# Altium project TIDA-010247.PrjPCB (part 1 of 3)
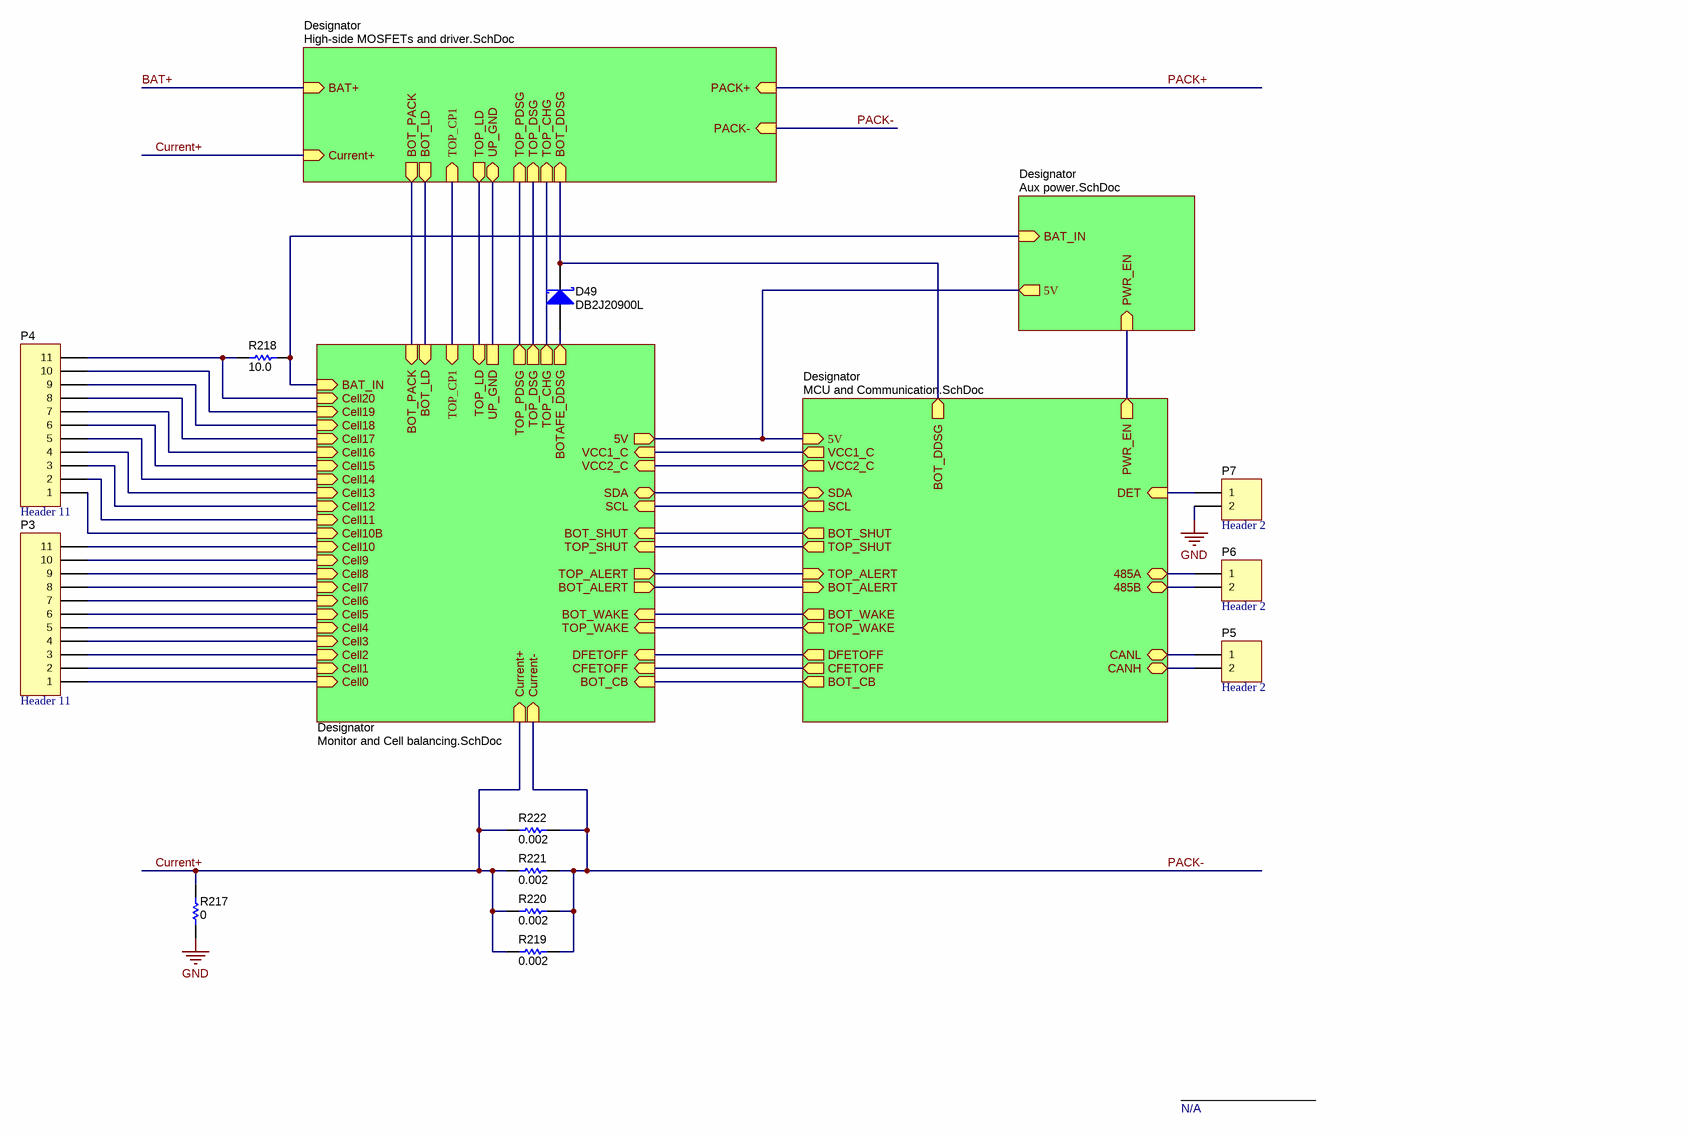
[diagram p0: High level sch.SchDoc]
TID: TIDA-010247; TechSupport: http://www.ti.com/support; SCH_Rev: E1; PRJ_Title: Up to 32s high side N-MOSFET; PRJ_Number: TIDA-010247; PRJ_Engineer: Ryan Tan; PRJ_Customer: Public Release; PCB_Rev: E1; PCB_Layout: Ryan Tan; CopyrightYear: 2021/11
7 sheets, 434 parts. Net scope: hierarchical (ports join the sheet entries above them; power ports are global).
Board file: v1.PcbDoc
Sheets:
  High level sch.SchDoc
    Designator = Monitor and Cell balancing.SchDoc
    Designator = Aux power.SchDoc
    Designator = MCU and Communication.SchDoc
    Designator = High-side MOSFETs and driver.SchDoc
    Designator = EVM_Hardware.SchDoc
    Designator = CoverSheet.SchDoc

## Sheet High level sch.SchDoc
size 431 x 279 mm; Date: Not shown in title block; ApprovedBy: Not shown in title block; CheckedBy: Not shown in title block; Author: Not shown in title block; CompanyName: Not shown in title block; Engineer: Not shown in title block; Organization: Not shown in title block; Address1: Not shown in title block; Address2: Not shown in title block; Address3: Not shown in title block; Address4: Not shown in title block; DocumentNumber: 2; Revision: Use project parameter SCH_Rev; SheetNumber: 2; SheetTotal: 7; PageSetup: Record=PageOptions¦CenterHorizontal=True¦CenterVertical=True¦PrintScale=1.00¦XCorrection=1.00¦YCorrection=1.00¦PrintKind=0¦BorderSize=5000000¦LeftOffset=0¦BottomOffset=0¦Orientation=2¦PaperLength=1000¦PaperWidth=1000¦Scale=100¦PaperSource=15¦PrintQuality=600¦MediaType=1¦DitherType=10¦PaperKind=Letter¦PrintScaleMode=1

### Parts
D49  DB2J20900L  [SOD-323F]
P3  Header 11  [XH Connector 11P]
P4  Header 11  [XH Connector 11P]
P5  Header 2  [HDR1X2]
P6  Header 2  [HDR1X2]
P7  Header 2  [HDR1X2]
R217  ValueDisplayed: 0  [0603]  (hidden comment: CRCW06030000Z0EA)
R218  ValueDisplayed: 10.0  [0603]  (hidden comment: RC0603FR-0710RL)
R219  ValueDisplayed: 0.002  [2512]  (hidden comment: CSNL2512FT2L00)
R220  ValueDisplayed: 0.002  [2512]  (hidden comment: CSNL2512FT2L00)
R221  ValueDisplayed: 0.002  [2512]  (hidden comment: CSNL2512FT2L00)
R222  ValueDisplayed: 0.002  [2512]  (hidden comment: CSNL2512FT2L00)

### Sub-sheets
Designator = Monitor and Cell balancing.SchDoc: Current+ (in), Current- (in), Cell0 (in), Cell15 (in), Cell1 (in), Cell16 (in), Cell3 (in), Cell6 (in), Cell2 (in), SDA (bidir), SCL (in), Cell11 (in), Cell10 (in), Cell7 (in), Cell12 (in), Cell9 (in), Cell4 (in), Cell8 (in), Cell5 (in), Cell13 (in), Cell14 (in), Cell17 (in), Cell18 (in), Cell20 (in), Cell19 (in), 5V (out), BOT_LD (in), BOT_SHUT (in), BOT_ALERT (out), BOT_WAKE (in), TOP_ALERT (out), TOP_SHUT (in), TOP_WAKE (in), BOT_PACK (in), DFETOFF (in), CFETOFF (in), BAT_IN (in), TOP_PDSG (out), TOP_DSG (out), TOP_CHG (out), TOP_LD (in), BOTAFE_DDSG (out), VCC2_C (in), VCC1_C (in), BOT_CB (in), UP_GND, Cell10B (in), TOP_CP1 (in)
Designator = Aux power.SchDoc: PWR_EN (in), BAT_IN (in), 5V (out)
Designator = MCU and Communication.SchDoc: PWR_EN (out), 485A (bidir), 485B (bidir), SCL (out), SDA (bidir), TOP_ALERT (in), BOT_SHUT (out), CANL (bidir), TOP_SHUT (out), TOP_WAKE (out), BOT_WAKE (out), BOT_ALERT (in), CANH (bidir), DFETOFF (out), CFETOFF (out), BOT_DDSG (out), VCC1_C (out), VCC2_C (out), BOT_CB (out), DET (in), 5V (in)
Designator = High-side MOSFETs and driver.SchDoc: PACK+ (in), BAT+ (in), BOT_LD (out), PACK- (in), BOT_PACK (out), TOP_DSG (in), TOP_LD (out), TOP_CHG (in), UP_GND (bidir), BOT_DDSG (in), TOP_PDSG (in), Current+ (in), TOP_CP1 (in)
Designator = EVM_Hardware.SchDoc: no entries
Designator = CoverSheet.SchDoc: no entries

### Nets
GND: P7.2 R217.1
UP_GND: sheet Designator/UP_GND, sheet Designator/UP_GND
5V: sheet Designator/5V, sheet Designator/5V, sheet Designator/5V
485A: P6.1 ; sheet Designator/485A
485B: P6.2 ; sheet Designator/485B
BAT_IN: R218.1 ; sheet Designator/BAT_IN, sheet Designator/BAT_IN
BOT_ALERT: sheet Designator/BOT_ALERT, sheet Designator/BOT_ALERT
BOT_CB: sheet Designator/BOT_CB, sheet Designator/BOT_CB
BOT_DDSG: D49.1(K) ; sheet Designator/BOT_DDSG, sheet Designator/BOT_DDSG
BOT_LD: sheet Designator/BOT_LD, sheet Designator/BOT_LD
BOT_PACK: sheet Designator/BOT_PACK, sheet Designator/BOT_PACK
BOT_SHUT: sheet Designator/BOT_SHUT, sheet Designator/BOT_SHUT
BOT_WAKE: sheet Designator/BOT_WAKE, sheet Designator/BOT_WAKE
BOTAFE_DDSG: D49.2(A) ; sheet Designator/BOTAFE_DDSG
CANH: P5.2 ; sheet Designator/CANH
CANL: P5.1 ; sheet Designator/CANL
Cell0: P3.1 ; sheet Designator/Cell0
Cell1: P3.2 ; sheet Designator/Cell1
Cell2: P3.3 ; sheet Designator/Cell2
Cell3: P3.4 ; sheet Designator/Cell3
Cell4: P3.5 ; sheet Designator/Cell4
Cell5: P3.6 ; sheet Designator/Cell5
Cell6: P3.7 ; sheet Designator/Cell6
Cell7: P3.8 ; sheet Designator/Cell7
Cell8: P3.9 ; sheet Designator/Cell8
Cell9: P3.10 ; sheet Designator/Cell9
Cell10: P3.11 ; sheet Designator/Cell10
Cell10B: P4.1 ; sheet Designator/Cell10B
Cell11: P4.2 ; sheet Designator/Cell11
Cell12: P4.3 ; sheet Designator/Cell12
Cell13: P4.4 ; sheet Designator/Cell13
Cell14: P4.5 ; sheet Designator/Cell14
Cell15: P4.6 ; sheet Designator/Cell15
Cell16: P4.7 ; sheet Designator/Cell16
Cell17: P4.8 ; sheet Designator/Cell17
Cell18: P4.9 ; sheet Designator/Cell18
Cell19: P4.10 ; sheet Designator/Cell19
Cell20: P4.11 R218.2 ; sheet Designator/Cell20
CFETOFF: sheet Designator/CFETOFF, sheet Designator/CFETOFF
Current+: R217.2 R219.1 R220.1 R221.1 R222.1 ; sheet Designator/Current+, sheet Designator/Current+
DET: P7.1 ; sheet Designator/DET
DFETOFF: sheet Designator/DFETOFF, sheet Designator/DFETOFF
PACK-: R219.2 R220.2 R221.2 R222.2 ; sheet Designator/Current-, sheet Designator/PACK-
PWR_EN: sheet Designator/PWR_EN, sheet Designator/PWR_EN
SCL: sheet Designator/SCL, sheet Designator/SCL
SDA: sheet Designator/SDA, sheet Designator/SDA
TOP_ALERT: sheet Designator/TOP_ALERT, sheet Designator/TOP_ALERT
TOP_CHG: sheet Designator/TOP_CHG, sheet Designator/TOP_CHG
TOP_CP1: sheet Designator/TOP_CP1, sheet Designator/TOP_CP1
TOP_DSG: sheet Designator/TOP_DSG, sheet Designator/TOP_DSG
TOP_LD: sheet Designator/TOP_LD, sheet Designator/TOP_LD
TOP_PDSG: sheet Designator/TOP_PDSG, sheet Designator/TOP_PDSG
TOP_SHUT: sheet Designator/TOP_SHUT, sheet Designator/TOP_SHUT
TOP_WAKE: sheet Designator/TOP_WAKE, sheet Designator/TOP_WAKE
VCC1_C: sheet Designator/VCC1_C, sheet Designator/VCC1_C
VCC2_C: sheet Designator/VCC2_C, sheet Designator/VCC2_C

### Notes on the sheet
- N/A

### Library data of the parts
D49 = DB2J20900L: Diode, Schottky, 20 V, 0.5 A, SOD-323F; Manufacturer: Panasonic; U/M: EA; Vf_V: 0.5; Value: 20V; Value1: 0.5A; Value2: 0.5V; Vr_V: 20; TJmax_C: 125; SizeAreaWB_mm2: 7.875; SizeArea_mm2: 3.125; SizeX_mm: 2.5; SizeY_mm: 1.25; SizeZ_mm: 0.8; AEC Category: Q101; AEC Qualified: N; Green_Lifecycle: Not Set; Green_REACh: Incomplete
P3 P4 = Header 11: Header, 11-Pin
P5-P7 = Header 2: Header, 2-Pin
R217 = CRCW06030000Z0EA: RES, 0, 5%, 0.1 W, 0603; Manufacturer: Vishay-Dale; CompType: Resistor; Value: 0; Value_Code: 0000; Tolerance_%: 5; Power_W: 0.1; Value2: 0.1W; VDC_V: 75; TempCo: 200 ppm/C; SizeArea_mm2: 1.28; SizeX_mm: 1.6; SizeY_mm: 0.8; SizeZ_mm: 1; EIA_Code: E24; U/M: EA; AEC Category: Q200; Green_Lifecycle: Active; Green_REACh: Passed
R218 = RC0603FR-0710RL: RES, 10.0, 1%, 0.1 W, 0603; Manufacturer: Yageo America; CompType: Resistor; Value: 10.0; Res_ohm: 10; Value_Code: 10R0; Tolerance_%: 1; Power_W: 0.1; Value2: 0.1W; VDC_V: 150; TempCo: 200 ppm/C; SizeArea_mm2: 1.28; SizeX_mm: 1.6; SizeY_mm: 0.8; EIA_Code: E96; U/M: EA; AEC Category: Q200; Green_Lifecycle: Active; Green_REACh: Passed
R219-R222 = CSNL2512FT2L00: RES, 0.002, 1%, 2 W, 2512; Manufacturer: Stackpole Electronics Inc; CompType: Resistor; Value: 0.002; Value_Code: 2L000; Tolerance_%: 1; Power_W: 2; Value2: 2W; VDC_V: 200; TempCo: 50 ppm/C; SizeArea_mm2: 20.16; SizeX_mm: 6.3; SizeY_mm: 3.2; SizeZ_mm: 0.71; U/M: EA; AEC Category: Q200

## Sheet Monitor and Cell balancing.SchDoc
size A2; Date: Not shown in title block; ApprovedBy: Not shown in title block; CheckedBy: Not shown in title block; Author: Not shown in title block; CompanyName: Not shown in title block; Engineer: Not shown in title block; Organization: Not shown in title block; Address1: Not shown in title block; Address2: Not shown in title block; Address3: Not shown in title block; Address4: Not shown in title block; DocumentNumber: 6; Revision: Use project parameter SCH_Rev; SheetNumber: 6; SheetTotal: 7; PageSetup: Record=PageOptions¦CenterHorizontal=True¦CenterVertical=True¦PrintScale=1.00¦XCorrection=1.00¦YCorrection=1.00¦PrintKind=0¦BorderSize=5000000¦LeftOffset=0¦BottomOffset=0¦Orientation=2¦PaperLength=1000¦PaperWidth=1000¦Scale=100¦PaperSource=15¦PrintQuality=600¦MediaType=1¦DitherType=10¦PaperKind=Letter¦PrintScaleMode=1
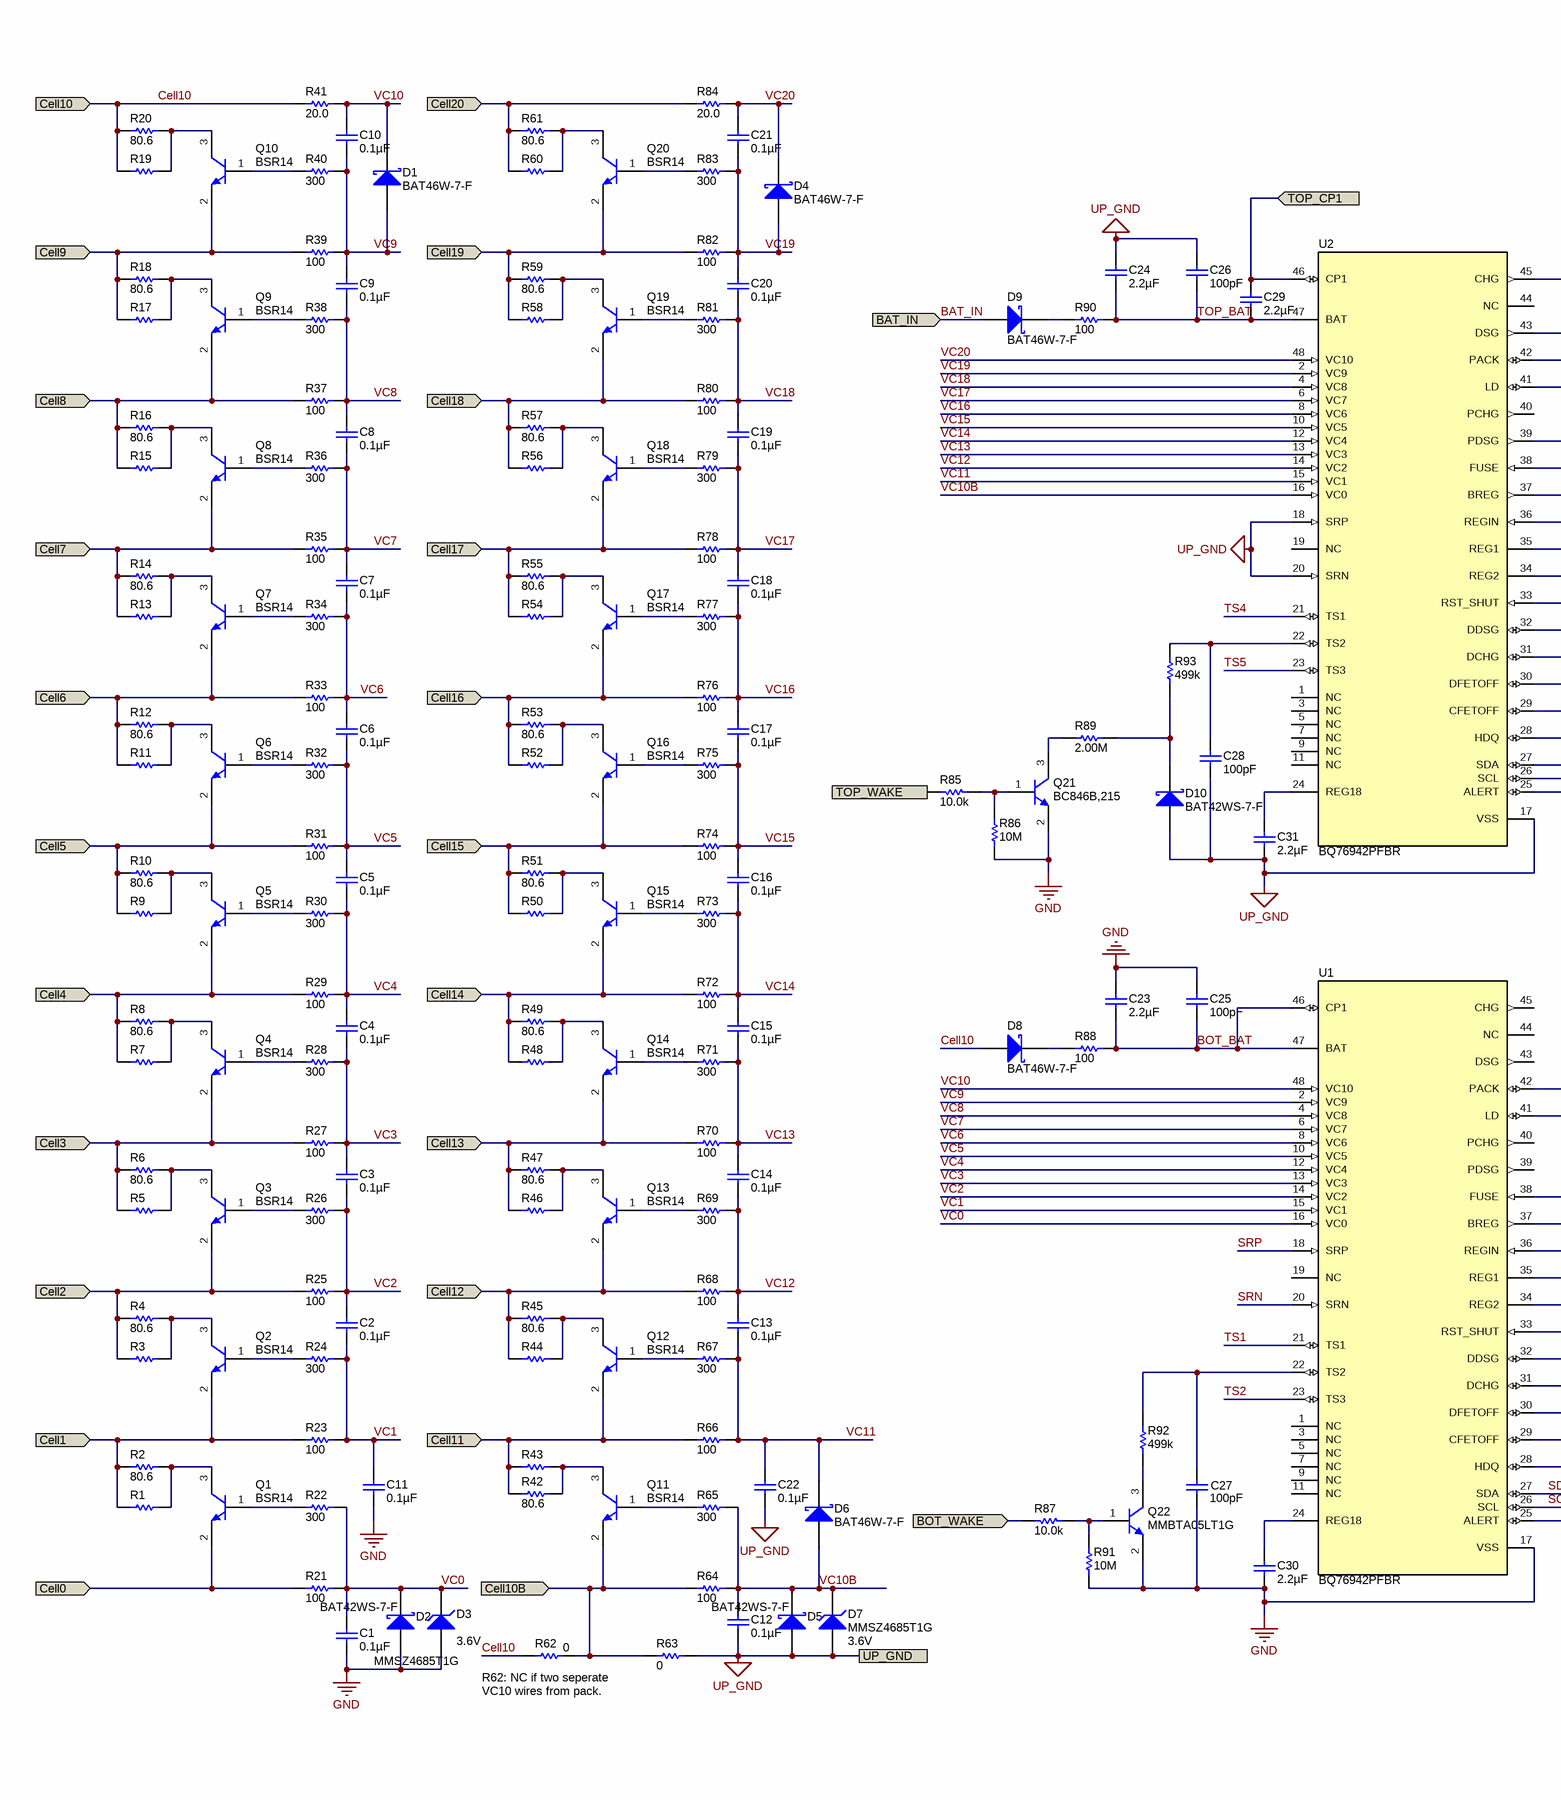
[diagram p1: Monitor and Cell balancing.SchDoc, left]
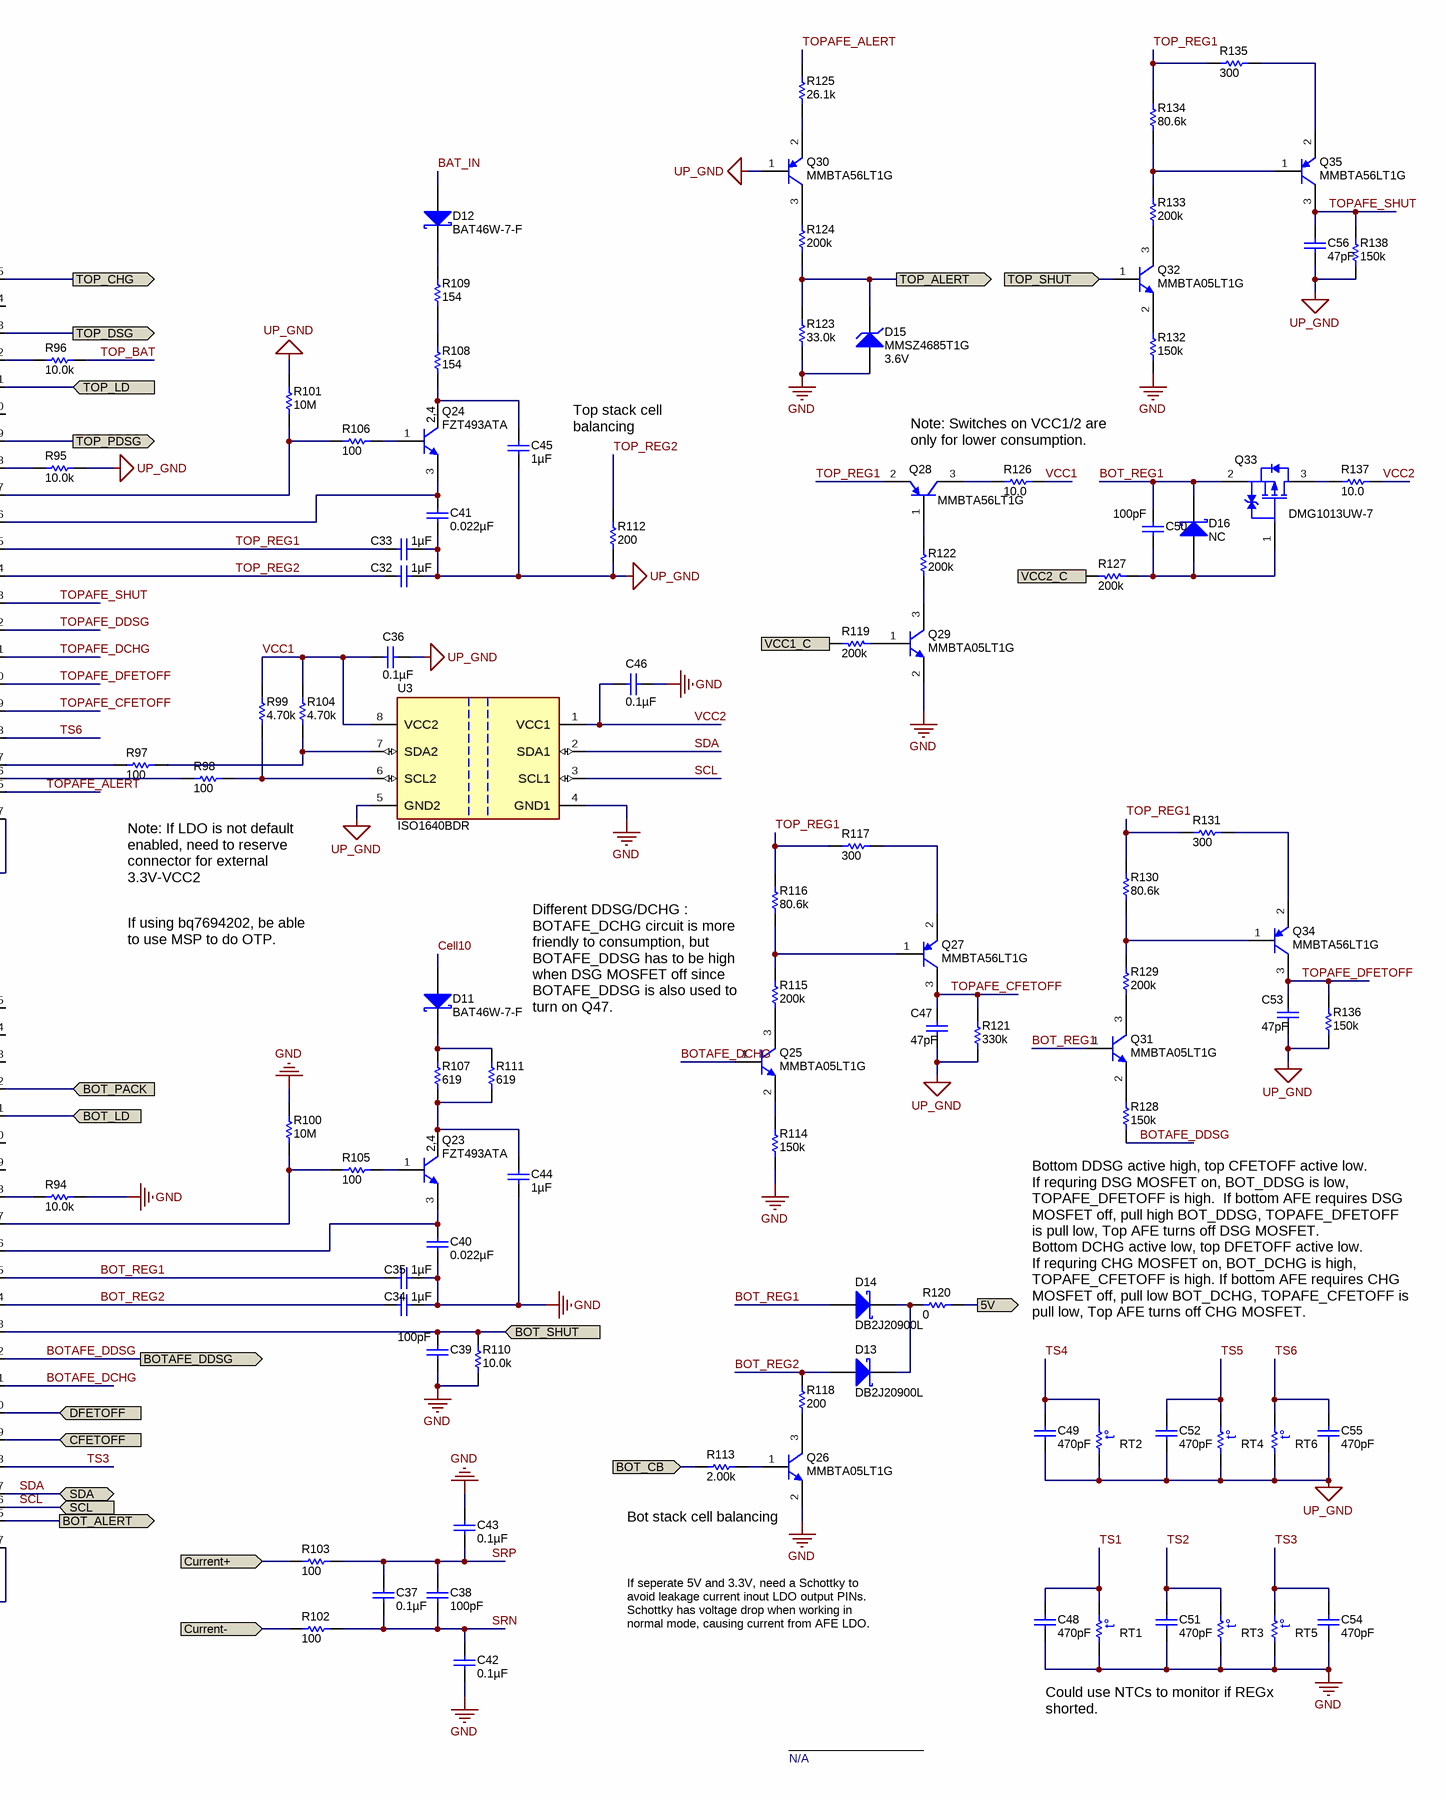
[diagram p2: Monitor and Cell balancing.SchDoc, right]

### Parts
C1  ValueDisplayed: 0.1µF  [0402]  (hidden comment: GRM155R71E104KE14D)
C2  ValueDisplayed: 0.1µF  [0402]  (hidden comment: GRM155R71E104KE14D)
C3  ValueDisplayed: 0.1µF  [0402]  (hidden comment: GRM155R71E104KE14D)
C4  ValueDisplayed: 0.1µF  [0402]  (hidden comment: GRM155R71E104KE14D)
C5  ValueDisplayed: 0.1µF  [0402]  (hidden comment: GRM155R71E104KE14D)
C6  ValueDisplayed: 0.1µF  [0402]  (hidden comment: GRM155R71E104KE14D)
C7  ValueDisplayed: 0.1µF  [0402]  (hidden comment: GRM155R71E104KE14D)
C8  ValueDisplayed: 0.1µF  [0402]  (hidden comment: GRM155R71E104KE14D)
C9  ValueDisplayed: 0.1µF  [0402]  (hidden comment: GRM155R71E104KE14D)
C10  ValueDisplayed: 0.1µF  [0402]  (hidden comment: GRM155R71E104KE14D)
C11  ValueDisplayed: 0.1µF  [0603S]  (hidden comment: GRM188R71H104KA93D)
C12  ValueDisplayed: 0.1µF  [0402]  (hidden comment: GRM155R71E104KE14D)
C13  ValueDisplayed: 0.1µF  [0402]  (hidden comment: GRM155R71E104KE14D)
C14  ValueDisplayed: 0.1µF  [0402]  (hidden comment: GRM155R71E104KE14D)
C15  ValueDisplayed: 0.1µF  [0402]  (hidden comment: GRM155R71E104KE14D)
C16  ValueDisplayed: 0.1µF  [0402]  (hidden comment: GRM155R71E104KE14D)
C17  ValueDisplayed: 0.1µF  [0402]  (hidden comment: GRM155R71E104KE14D)
C18  ValueDisplayed: 0.1µF  [0402]  (hidden comment: GRM155R71E104KE14D)
C19  ValueDisplayed: 0.1µF  [0402]  (hidden comment: GRM155R71E104KE14D)
C20  ValueDisplayed: 0.1µF  [0402]  (hidden comment: GRM155R71E104KE14D)
C21  ValueDisplayed: 0.1µF  [0402]  (hidden comment: GRM155R71E104KE14D)
C22  ValueDisplayed: 0.1µF  [0603S]  (hidden comment: GRM188R71H104KA93D)
C23  ValueDisplayed: 2.2µF  [1206_190]  (hidden comment: C1206X225K101TX)
C24  ValueDisplayed: 2.2µF  [1206_190]  (hidden comment: C1206X225K101TX)
C25  ValueDisplayed: 100pF  [0603]  (hidden comment: GRM1885C2A101JA01D)
C26  ValueDisplayed: 100pF  [0603]  (hidden comment: GRM1885C2A101JA01D)
C27  ValueDisplayed: 100pF  [0603]  (hidden comment: GRM1885C2A101JA01D)
C28  ValueDisplayed: 100pF  [0603]  (hidden comment: GRM1885C2A101JA01D)
C29  ValueDisplayed: 2.2µF  [0805_HV]  (hidden comment: GRM21BR71E225KA73L)
C30  ValueDisplayed: 2.2µF  [0603]  (hidden comment: EMK107BB7225MA-T)
C31  ValueDisplayed: 2.2µF  [0603]  (hidden comment: EMK107BB7225MA-T)
C32  ValueDisplayed: 1µF  [0603]  (hidden comment: GCM188R71C105KA64D)
C33  ValueDisplayed: 1µF  [0603]  (hidden comment: GCM188R71C105KA64D)
C34  ValueDisplayed: 1µF  [0603]  (hidden comment: GCM188R71C105KA64D)
C35  ValueDisplayed: 1µF  [0603]  (hidden comment: GCM188R71C105KA64D)
C36  ValueDisplayed: 0.1µF  [0603]  (hidden comment: GRM188R71H104KA93D)
C37  ValueDisplayed: 0.1µF  [0603]  (hidden comment: GRM188R71H104KA93D)
C38  ValueDisplayed: 100pF  [0603]  (hidden comment: GRM1885C2A101JA01D)
C39  ValueDisplayed: 100pF  [0603]  (hidden comment: GRM1885C2A101JA01D)
C40  ValueDisplayed: 0.022µF  [0603S]  (hidden comment: GRM188R71H223KA01D)
C41  ValueDisplayed: 0.022µF  [0603]  (hidden comment: GRM188R71H223KA01D)
C42  ValueDisplayed: 0.1µF  [0603]  (hidden comment: GRM188R71H104KA93D)
C43  ValueDisplayed: 0.1µF  [0603]  (hidden comment: GRM188R71H104KA93D)
C44  ValueDisplayed: 1µF  [1206_180]  (hidden comment: C3216X7R2A105K160AA)
C45  ValueDisplayed: 1µF  [1206_180]  (hidden comment: C3216X7R2A105K160AA)
C46  ValueDisplayed: 0.1µF  [0603]  (hidden comment: GRM188R71H104KA93D)
C47  ValueDisplayed: 47pF  [0603]  (hidden comment: GRM1885C1H470JA01D)
C48  ValueDisplayed: 470pF  [0603]  (hidden comment: GRM188R71H471KA01D)
C49  ValueDisplayed: 470pF  [0603]  (hidden comment: GRM188R71H471KA01D)
C50  ValueDisplayed: 100pF  [0603]  (hidden comment: GRM1885C2A101JA01D)
C51  ValueDisplayed: 470pF  [0603]  (hidden comment: GRM188R71H471KA01D)
C52  ValueDisplayed: 470pF  [0603]  (hidden comment: GRM188R71H471KA01D)
C53  ValueDisplayed: 47pF  [0603]  (hidden comment: GRM1885C1H470JA01D)
C54  ValueDisplayed: 470pF  [0603]  (hidden comment: GRM188R71H471KA01D)
C55  ValueDisplayed: 470pF  [0603]  (hidden comment: GRM188R71H471KA01D)
C56  ValueDisplayed: 47pF  [0603]  (hidden comment: GRM1885C1H470JA01D)
D1  BAT46W-7-F  [SOD-123]
D2  BAT42WS-7-F  [SOD-323]
D3  MMSZ4685T1G  value 3.6V  [SOD-123]
D4  BAT46W-7-F  [SOD-123]
D5  BAT42WS-7-F  [SOD-323]
D6  BAT46W-7-F  [SOD-123]
D7  MMSZ4685T1G  value 3.6V  [SOD-123]
D8  BAT46W-7-F  [SOD-123]
D9  BAT46W-7-F  [SOD-123]
D10  BAT42WS-7-F  [SOD-323]
D11  BAT46W-7-F  [SOD-123]
D12  BAT46W-7-F  [SOD-123]
D13  DB2J20900L  [SOD-323F]
D14  DB2J20900L  [SOD-323F]
D15  MMSZ4685T1G  value 3.6V  [SOD-123]
D16  NC  [SOD-323]
Q1  BSR14  [SOT-23]
Q2  BSR14  [SOT-23]
Q3  BSR14  [SOT-23]
Q4  BSR14  [SOT-23]
Q5  BSR14  [SOT-23]
Q6  BSR14  [SOT-23]
Q7  BSR14  [SOT-23]
Q8  BSR14  [SOT-23]
Q9  BSR14  [SOT-23]
Q10  BSR14  [SOT-23]
Q11  BSR14  [SOT-23]
Q12  BSR14  [SOT-23]
Q13  BSR14  [SOT-23]
Q14  BSR14  [SOT-23]
Q15  BSR14  [SOT-23]
Q16  BSR14  [SOT-23]
Q17  BSR14  [SOT-23]
Q18  BSR14  [SOT-23]
Q19  BSR14  [SOT-23]
Q20  BSR14  [SOT-23]
Q21  BC846B,215  [SOT-23]
Q22  MMBTA05LT1G  [SOT-23]
Q23  FZT493ATA  [SOT-223]
Q24  FZT493ATA  [SOT-223]
Q25  MMBTA05LT1G  [SOT-23]
Q26  MMBTA05LT1G  [SOT-23]
Q27  MMBTA56LT1G  [SOT-23]
Q28  MMBTA56LT1G  [SOT-23]
Q29  MMBTA05LT1G  [SOT-23]
Q30  MMBTA56LT1G  [SOT-23]
Q31  MMBTA05LT1G  [SOT-23]
Q32  MMBTA05LT1G  [SOT-23]
Q33  DMG1013UW-7  [SOT-323]
Q34  MMBTA56LT1G  [SOT-23]
Q35  MMBTA56LT1G  [SOT-23]
R1  CRCW120680R6FKEA  [1206]  (value not drawn)
R2  ValueDisplayed: 80.6  [1206]  (hidden comment: CRCW120680R6FKEA)
R3  CRCW120680R6FKEA  [1206]  (value not drawn)
R4  ValueDisplayed: 80.6  [1206]  (hidden comment: CRCW120680R6FKEA)
R5  CRCW120680R6FKEA  [1206]  (value not drawn)
R6  ValueDisplayed: 80.6  [1206]  (hidden comment: CRCW120680R6FKEA)
R7  CRCW120680R6FKEA  [1206]  (value not drawn)
R8  ValueDisplayed: 80.6  [1206]  (hidden comment: CRCW120680R6FKEA)
R9  CRCW120680R6FKEA  [1206]  (value not drawn)
R10  ValueDisplayed: 80.6  [1206]  (hidden comment: CRCW120680R6FKEA)
R11  CRCW120680R6FKEA  [1206]  (value not drawn)
R12  ValueDisplayed: 80.6  [1206]  (hidden comment: CRCW120680R6FKEA)
R13  CRCW120680R6FKEA  [1206]  (value not drawn)
R14  ValueDisplayed: 80.6  [1206]  (hidden comment: CRCW120680R6FKEA)
R15  CRCW120680R6FKEA  [1206]  (value not drawn)
R16  ValueDisplayed: 80.6  [1206]  (hidden comment: CRCW120680R6FKEA)
R17  CRCW120680R6FKEA  [1206]  (value not drawn)
R18  ValueDisplayed: 80.6  [1206]  (hidden comment: CRCW120680R6FKEA)
R19  CRCW120680R6FKEA  [1206]  (value not drawn)
R20  ValueDisplayed: 80.6  [1206]  (hidden comment: CRCW120680R6FKEA)
R21  ValueDisplayed: 100  [0603]  (hidden comment: CRCW0603100RFKEA)
R22  ValueDisplayed: 300  [0603]  (hidden comment: CRCW0603300RJNEA)
R23  ValueDisplayed: 100  [0603]  (hidden comment: CRCW0603100RFKEA)
R24  ValueDisplayed: 300  [0603]  (hidden comment: CRCW0603300RJNEA)
R25  ValueDisplayed: 100  [0603]  (hidden comment: CRCW0603100RFKEA)
R26  ValueDisplayed: 300  [0603]  (hidden comment: CRCW0603300RJNEA)
R27  ValueDisplayed: 100  [0603]  (hidden comment: CRCW0603100RFKEA)
R28  ValueDisplayed: 300  [0603]  (hidden comment: CRCW0603300RJNEA)
R29  ValueDisplayed: 100  [0603]  (hidden comment: CRCW0603100RFKEA)
R30  ValueDisplayed: 300  [0603]  (hidden comment: CRCW0603300RJNEA)
R31  ValueDisplayed: 100  [0603]  (hidden comment: CRCW0603100RFKEA)
R32  ValueDisplayed: 300  [0603]  (hidden comment: CRCW0603300RJNEA)
R33  ValueDisplayed: 100  [0603]  (hidden comment: CRCW0603100RFKEA)
R34  ValueDisplayed: 300  [0603]  (hidden comment: CRCW0603300RJNEA)
R35  ValueDisplayed: 100  [0603]  (hidden comment: CRCW0603100RFKEA)
R36  ValueDisplayed: 300  [0603]  (hidden comment: CRCW0603300RJNEA)
R37  ValueDisplayed: 100  [0603]  (hidden comment: CRCW0603100RFKEA)
R38  ValueDisplayed: 300  [0603]  (hidden comment: CRCW0603300RJNEA)
R39  ValueDisplayed: 100  [0603]  (hidden comment: CRCW0603100RFKEA)
R40  ValueDisplayed: 300  [0603]  (hidden comment: CRCW0603300RJNEA)
R41  ValueDisplayed: 20.0  [0603]  (hidden comment: CRCW060320R0FKEA)
R42  ValueDisplayed: 80.6  [1206]  (hidden comment: CRCW120680R6FKEA)
R43  CRCW120680R6FKEA  [1206]  (value not drawn)
R44  CRCW120680R6FKEA  [1206]  (value not drawn)
R45  ValueDisplayed: 80.6  [1206]  (hidden comment: CRCW120680R6FKEA)
R46  CRCW120680R6FKEA  [1206]  (value not drawn)
R47  ValueDisplayed: 80.6  [1206]  (hidden comment: CRCW120680R6FKEA)
R48  CRCW120680R6FKEA  [1206]  (value not drawn)
R49  ValueDisplayed: 80.6  [1206]  (hidden comment: CRCW120680R6FKEA)
R50  CRCW120680R6FKEA  [1206]  (value not drawn)
R51  ValueDisplayed: 80.6  [1206]  (hidden comment: CRCW120680R6FKEA)
R52  CRCW120680R6FKEA  [1206]  (value not drawn)
R53  ValueDisplayed: 80.6  [1206]  (hidden comment: CRCW120680R6FKEA)
R54  CRCW120680R6FKEA  [1206]  (value not drawn)
R55  ValueDisplayed: 80.6  [1206]  (hidden comment: CRCW120680R6FKEA)
R56  CRCW120680R6FKEA  [1206]  (value not drawn)
R57  ValueDisplayed: 80.6  [1206]  (hidden comment: CRCW120680R6FKEA)
R58  CRCW120680R6FKEA  [1206]  (value not drawn)
R59  ValueDisplayed: 80.6  [1206]  (hidden comment: CRCW120680R6FKEA)
R60  CRCW120680R6FKEA  [1206]  (value not drawn)
R61  ValueDisplayed: 80.6  [1206]  (hidden comment: CRCW120680R6FKEA)
R62  ValueDisplayed: 0  [0603]  (hidden comment: CRCW06030000Z0EA)
R63  ValueDisplayed: 0  [0603]  (hidden comment: CRCW06030000Z0EA)
R64  ValueDisplayed: 100  [0603]  (hidden comment: CRCW0603100RFKEA)
R65  ValueDisplayed: 300  [0603]  (hidden comment: CRCW0603300RJNEA)
R66  ValueDisplayed: 100  [0603]  (hidden comment: CRCW0603100RFKEA)
R67  ValueDisplayed: 300  [0603]  (hidden comment: CRCW0603300RJNEA)
R68  ValueDisplayed: 100  [0603]  (hidden comment: CRCW0603100RFKEA)
R69  ValueDisplayed: 300  [0603]  (hidden comment: CRCW0603300RJNEA)
R70  ValueDisplayed: 100  [0603]  (hidden comment: CRCW0603100RFKEA)
R71  ValueDisplayed: 300  [0603]  (hidden comment: CRCW0603300RJNEA)
R72  ValueDisplayed: 100  [0603]  (hidden comment: CRCW0603100RFKEA)
R73  ValueDisplayed: 300  [0603]  (hidden comment: CRCW0603300RJNEA)
R74  ValueDisplayed: 100  [0603]  (hidden comment: CRCW0603100RFKEA)
R75  ValueDisplayed: 300  [0603]  (hidden comment: CRCW0603300RJNEA)
R76  ValueDisplayed: 100  [0603]  (hidden comment: CRCW0603100RFKEA)
R77  ValueDisplayed: 300  [0603]  (hidden comment: CRCW0603300RJNEA)
R78  ValueDisplayed: 100  [0603]  (hidden comment: CRCW0603100RFKEA)
R79  ValueDisplayed: 300  [0603]  (hidden comment: CRCW0603300RJNEA)
R80  ValueDisplayed: 100  [0603]  (hidden comment: CRCW0603100RFKEA)
R81  ValueDisplayed: 300  [0603]  (hidden comment: CRCW0603300RJNEA)
R82  ValueDisplayed: 100  [0603]  (hidden comment: CRCW0603100RFKEA)
R83  ValueDisplayed: 300  [0603]  (hidden comment: CRCW0603300RJNEA)
R84  ValueDisplayed: 20.0  [0603]  (hidden comment: CRCW060320R0FKEA)
R85  ValueDisplayed: 10.0k  [0603]  (hidden comment: CRCW060310K0FKEA)
R86  ValueDisplayed: 10M  [0603]  (hidden comment: CRCW060310M0JNEA)
R87  ValueDisplayed: 10.0k  [0603]  (hidden comment: CRCW060310K0FKEA)
R88  ValueDisplayed: 100  [0603]  (hidden comment: CRCW0603100RFKEA)
R89  ValueDisplayed: 2.00M  [0603]  (hidden comment: RC0603FR-072ML)
R90  ValueDisplayed: 100  [0603]  (hidden comment: CRCW0603100RFKEA)
R91  ValueDisplayed: 10M  [0603]  (hidden comment: CRCW060310M0JNEA)
R92  ValueDisplayed: 499k  [0603]  (hidden comment: CRCW0603499KFKEA)
R93  ValueDisplayed: 499k  [0603]  (hidden comment: CRCW0603499KFKEA)
R94  ValueDisplayed: 10.0k  [0603]  (hidden comment: CRCW060310K0FKEA)
R95  ValueDisplayed: 10.0k  [0603]  (hidden comment: CRCW060310K0FKEA)
R96  ValueDisplayed: 10.0k  [0603]  (hidden comment: CRCW060310K0FKEA)
R97  ValueDisplayed: 100  [0603]  (hidden comment: CRCW0603100RFKEA)
R98  ValueDisplayed: 100  [0603]  (hidden comment: CRCW0603100RFKEA)
R99  ValueDisplayed: 4.70k  [0603]  (hidden comment: RC0603FR-074K7L)
R100  ValueDisplayed: 10M  [0603]  (hidden comment: CRCW060310M0JNEA)
R101  ValueDisplayed: 10M  [0603]  (hidden comment: CRCW060310M0JNEA)
R102  ValueDisplayed: 100  [0603]  (hidden comment: CRCW0603100RFKEA)
R103  ValueDisplayed: 100  [0603]  (hidden comment: CRCW0603100RFKEA)
R104  ValueDisplayed: 4.70k  [0603]  (hidden comment: RC0603FR-074K7L)
R105  ValueDisplayed: 100  [0603]  (hidden comment: CRCW0603100RFKEA)
R106  ValueDisplayed: 100  [0603]  (hidden comment: CRCW0603100RFKEA)
R107  ValueDisplayed: 619  [1206]  (hidden comment: RC1206FR-07619RL)
R108  ValueDisplayed: 154  [1206]  (hidden comment: AC1206FR-07154RL)
R109  ValueDisplayed: 154  [1206]  (hidden comment: AC1206FR-07154RL)
R110  ValueDisplayed: 10.0k  [0603]  (hidden comment: CRCW060310K0FKEA)
R111  ValueDisplayed: 619  [1206]  (hidden comment: RC1206FR-07619RL)
R112  ValueDisplayed: 200  [2512]  (hidden comment: RC2512JK-07200RL)
R113  ValueDisplayed: 2.00k  [0603]  (hidden comment: RC0603FR-072KL)
R114  ValueDisplayed: 150k  [0603]  (hidden comment: CRCW0603150KFKEA)
R115  ValueDisplayed: 200k  [0603]  (hidden comment: CRCW0603200KFKEA)
R116  ValueDisplayed: 80.6k  [0603]  (hidden comment: CRCW060380K6FKEA)
R117  ValueDisplayed: 300  [0603]  (hidden comment: RC0603FR-07300RL)
R118  ValueDisplayed: 200  [2512]  (hidden comment: RC2512JK-07200RL)
R119  ValueDisplayed: 200k  [0603]  (hidden comment: CRCW0603200KFKEA)
R120  ValueDisplayed: 0  [0603]  (hidden comment: CRCW06030000Z0EA)
R121  ValueDisplayed: 330k  [0603]  (hidden comment: CRCW0603330KJNEA)
R122  ValueDisplayed: 200k  [0603]  (hidden comment: CRCW0603200KFKEA)
R123  ValueDisplayed: 33.0k  [0603]  (hidden comment: RC0603FR-0733KL)
R124  ValueDisplayed: 200k  [0603]  (hidden comment: CRCW0603200KFKEA)
R125  ValueDisplayed: 26.1k  [0603]  (hidden comment: CRCW060326K1FKEA)
R126  ValueDisplayed: 10.0  [0603]  (hidden comment: RC0603FR-0710RL)
R127  ValueDisplayed: 200k  [0603]  (hidden comment: CRCW0603200KFKEA)
R128  ValueDisplayed: 150k  [0603]  (hidden comment: CRCW0603150KFKEA)
R129  ValueDisplayed: 200k  [0603]  (hidden comment: CRCW0603200KFKEA)
R130  ValueDisplayed: 80.6k  [0603]  (hidden comment: CRCW060380K6FKEA)
R131  ValueDisplayed: 300  [0603]  (hidden comment: RC0603FR-07300RL)
R132  ValueDisplayed: 150k  [0603]  (hidden comment: CRCW0603150KFKEA)
R133  ValueDisplayed: 200k  [0603]  (hidden comment: CRCW0603200KFKEA)
R134  ValueDisplayed: 80.6k  [0603]  (hidden comment: CRCW060380K6FKEA)
R135  ValueDisplayed: 300  [0603]  (hidden comment: RC0603FR-07300RL)
R136  ValueDisplayed: 150k  [0603]  (hidden comment: CRCW0603150KFKEA)
R137  ValueDisplayed: 10.0  [0603]  (hidden comment: RC0603FR-0710RL)
R138  ValueDisplayed: 150k  [0603]  (hidden comment: CRCW0603150KFKEA)
RT1  MF51E103F3950  [Thermistor_103AT-2]  (value not drawn)
RT2  MF51E103F3950  [Thermistor_103AT-2]  (value not drawn)
RT3  MF51E103F3950  [Thermistor_103AT-2]  (value not drawn)
RT4  MF51E103F3950  [Thermistor_103AT-2]  (value not drawn)
RT5  MF51E103F3950  [Thermistor_103AT-2]  (value not drawn)
RT6  MF51E103F3950  [Thermistor_103AT-2]  (value not drawn)
U1  BQ76942PFBR  [PFB0048A_N]
U2  BQ76942PFBR  [PFB0048A_N]
U3  ISO1640BDR  [D0008A-MFG]

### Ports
5V (out), BAT_IN (in), BOT_ALERT (out), BOT_CB (in), BOT_LD (in), BOT_PACK (in), BOT_SHUT (in), BOT_WAKE (in), BOTAFE_DDSG (out), Cell0 (in), Cell1 (in), Cell2 (in), Cell3 (in), Cell4 (in), Cell5 (in), Cell6 (in), Cell7 (in), Cell8 (in), Cell9 (in), Cell10 (in), Cell10B (in), Cell11 (in), Cell12 (in), Cell13 (in), Cell14 (in), Cell15 (in), Cell16 (in), Cell17 (in), Cell18 (in), Cell19 (in), Cell20 (in), CFETOFF (in), Current+ (in), Current- (in), DFETOFF (in), SCL (in), SDA (bidir), TOP_ALERT (out), TOP_CHG (out), TOP_CP1 (in), TOP_DSG (out), TOP_LD (in), TOP_PDSG (out), TOP_SHUT (in), TOP_WAKE (in), UP_GND, VCC1_C (in), VCC2_C (in)

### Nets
GND: C1.2 C11.2 C23.1 C25.1 C27.2 C30.2 C34.2 C35.2 C39.2 C40.2 C42.2 C43.1 C44.2 C46.2 C48.2 C51.2 C54.2 D2.2(A) D3.2(A) D15.2(A) Q21.2(E) Q22.2(E) Q26.2(E) Q29.2(E) R86.2 R91.2 R94.1 R100.2 R110.1 R114.1 R123.1 R132.1 RT1.1 RT3.1 RT5.1 U1.17(VSS) U3.4(GND1)
UP_GND: C12.2 C22.2 C24.1 C26.1 C28.2 C31.2 C32.2 C33.2 C36.2 C41.2 C45.2 C47.2 C49.2 C52.2 C53.2 C55.2 C56.2 D5.2(A) D7.2(A) D10.2(A) Q30.1(B) R63.1 R95.1 R101.2 R112.2 R121.1 R136.1 R138.1 RT2.1 RT4.1 RT6.1 U2.17(VSS) U2.18(SRP) U2.20(SRN) U3.5(GND2) ; port UP_GND
5V: R120.2 ; port 5V
BAT_IN: D9.2(A) D12.2(A) ; port BAT_IN
BOT_ALERT: U1.25(ALERT) ; port BOT_ALERT
BOT_BAT: C23.2 C25.2 R88.2 U1.46(CP1) U1.47(BAT)
BOT_CB: R113.1 ; port BOT_CB
BOT_LD: U1.41(LD) ; port BOT_LD
BOT_PACK: U1.42(PACK) ; port BOT_PACK
BOT_REG1: C35.1 C50.1 D14.2(A) D16.1(K) Q31.1(B) Q33.2(S) U1.35(REG1)
BOT_REG2: C34.1 D13.2(A) R118.2 U1.34(REG2)
BOT_SHUT: C39.1 R110.2 U1.33(RST_SHUT) ; port BOT_SHUT
BOT_WAKE: R87.1 ; port BOT_WAKE
BOTAFE_DCHG: Q25.1(B) U1.31(DCHG)
BOTAFE_DDSG: R128.1 U1.32(DDSG) ; port BOTAFE_DDSG
Cell0: Q1.2(E) R21.1 ; port Cell0
Cell1: Q2.2(E) R1.1 R2.1 R23.1 ; port Cell1
Cell2: Q3.2(E) R3.1 R4.1 R25.1 ; port Cell2
Cell3: Q4.2(E) R5.1 R6.1 R27.1 ; port Cell3
Cell4: Q5.2(E) R7.1 R8.1 R29.1 ; port Cell4
Cell5: Q6.2(E) R9.1 R10.1 R31.1 ; port Cell5
Cell6: Q7.2(E) R11.1 R12.1 R33.1 ; port Cell6
Cell7: Q8.2(E) R13.1 R14.1 R35.1 ; port Cell7
Cell8: Q9.2(E) R15.1 R16.1 R37.1 ; port Cell8
Cell9: Q10.2(E) R17.1 R18.1 R39.1 ; port Cell9
Cell10: D8.2(A) D11.2(A) R19.1 R20.1 R41.1 R62.2 ; port Cell10
Cell10B: Q11.2(E) R62.1 R63.2 R64.1 ; port Cell10B
Cell11: Q12.2(E) R42.1 R43.1 R66.1 ; port Cell11
Cell12: Q13.2(E) R44.1 R45.1 R68.1 ; port Cell12
Cell13: Q14.2(E) R46.1 R47.1 R70.1 ; port Cell13
Cell14: Q15.2(E) R48.1 R49.1 R72.1 ; port Cell14
Cell15: Q16.2(E) R50.1 R51.1 R74.1 ; port Cell15
Cell16: Q17.2(E) R52.1 R53.1 R76.1 ; port Cell16
Cell17: Q18.2(E) R54.1 R55.1 R78.1 ; port Cell17
Cell18: Q19.2(E) R56.1 R57.1 R80.1 ; port Cell18
Cell19: Q20.2(E) R58.1 R59.1 R82.1 ; port Cell19
Cell20: R60.1 R61.1 R84.1 ; port Cell20
CFETOFF: U1.29(CFETOFF) ; port CFETOFF
Current+: R103.1 ; port Current+
DFETOFF: U1.30(DFETOFF) ; port DFETOFF
PACK-: R102.1 ; port Current-
SCL: U1.26(SCL) U3.3(SCL1) ; port SCL
SDA: U1.27(SDA) U3.2(SDA1) ; port SDA
SRN: C37.2 C38.2 C42.1 R102.2 U1.20(SRN)
SRP: C37.1 C38.1 C43.2 R103.2 U1.18(SRP)
TOP_ALERT: D15.1(K) R123.2 R124.2 ; port TOP_ALERT
TOP_BAT: C24.2 C26.2 C29.2 R90.2 R96.1 U2.47(BAT)
TOP_CHG: U2.45(CHG) ; port TOP_CHG
TOP_CP1: C29.1 U2.46(CP1) ; port TOP_CP1
TOP_DSG: U2.43(DSG) ; port TOP_DSG
TOP_LD: U2.41(LD) ; port TOP_LD
TOP_PDSG: U2.39(PDSG) ; port TOP_PDSG
TOP_REG1: C33.1 Q28.2(E) R116.2 R117.2 R130.2 R131.2 R134.2 R135.2 U2.35(REG1)
TOP_REG2: C32.1 R112.1 U2.34(REG2)
TOP_SHUT: Q32.1(B) ; port TOP_SHUT
TOP_WAKE: R85.1 ; port TOP_WAKE
TOPAFE_ALERT: R125.2 U2.25(ALERT)
TOPAFE_CFETOFF: C47.1 Q27.3(C) R121.2 U2.29(CFETOFF)
TOPAFE_DCHG: U2.31(DCHG)
TOPAFE_DDSG: U2.32(DDSG)
TOPAFE_DFETOFF: C53.1 Q34.3(C) R136.2 U2.30(DFETOFF)
TOPAFE_SHUT: C56.1 Q35.3(C) R138.2 U2.33(RST_SHUT)
TS1: C48.1 RT1.2 U1.21(TS1)
TS2: C51.1 RT3.2 U1.23(TS3)
TS3: C54.1 RT5.2 U1.28(HDQ)
TS4: C49.1 RT2.2 U2.21(TS1)
TS5: C52.1 RT4.2 U2.23(TS3)
TS6: C55.1 RT6.2 U2.28(HDQ)
VC0: C1.1 D2.1(K) D3.1(K) R21.2 R22.2 U1.16(VC0)
VC1: C2.2 C11.1 R23.2 R24.2 U1.15(VC1)
VC2: C2.1 C3.2 R25.2 R26.2 U1.14(VC2)
VC3: C3.1 C4.2 R27.2 R28.2 U1.13(VC3)
VC4: C4.1 C5.2 R29.2 R30.2 U1.12(VC4)
VC5: C5.1 C6.2 R31.2 R32.2 U1.10(VC5)
VC6: C6.1 C7.2 R33.2 R34.2 U1.8(VC6)
VC7: C7.1 C8.2 R35.2 R36.2 U1.6(VC7)
VC8: C8.1 C9.2 R37.2 R38.2 U1.4(VC8)
VC9: C9.1 C10.2 D1.2(A) R39.2 R40.2 U1.2(VC9)
VC10: C10.1 D1.1(K) R41.2 U1.48(VC10)
VC10B: C12.1 D5.1(K) D6.2(A) D7.1(K) R64.2 R65.2 U2.16(VC0)
VC11: C13.2 C22.1 D6.1(K) R66.2 R67.2 U2.15(VC1)
VC12: C13.1 C14.2 R68.2 R69.2 U2.14(VC2)
VC13: C14.1 C15.2 R70.2 R71.2 U2.13(VC3)
VC14: C15.1 C16.2 R72.2 R73.2 U2.12(VC4)
VC15: C16.1 C17.2 R74.2 R75.2 U2.10(VC5)
VC16: C17.1 C18.2 R76.2 R77.2 U2.8(VC6)
VC17: C18.1 C19.2 R78.2 R79.2 U2.6(VC7)
VC18: C19.1 C20.2 R80.2 R81.2 U2.4(VC8)
VC19: C20.1 C21.2 D4.2(A) R82.2 R83.2 U2.2(VC9)
VC20: C21.1 D4.1(K) R84.2 U2.48(VC10)
VCC1: C36.1 R99.2 R104.2 R126.2 U3.8(VCC2)
VCC1_C: R119.1 ; port VCC1_C
VCC2: C46.1 R137.2 U3.1(VCC1)
VCC2_C: R127.1 ; port VCC2_C
NetC27_1: C27.1 R92.2 U1.22(TS2)
NetC28_1: C28.1 R93.2 U2.22(TS2)
NetC30_1: C30.1 U1.24(REG18)
NetC31_1: C31.1 U2.24(REG18)
NetC40_1: C40.1 Q23.3(E) U1.36(REGIN)
NetC41_1: C41.1 Q24.3(E) U2.36(REGIN)
NetC44_1: C44.1 Q23.2(C) Q23.4(C) R107.1 R111.1
NetC45_1: C45.1 Q24.2(C) Q24.4(C) R108.1
NetC50_2: C50.2 D16.2(A) Q33.1(G) R127.2
NetD8_1: D8.1(K) R88.1
NetD9_1: D9.1(K) R90.1
NetD10_1: D10.1(K) R89.2 R93.1
NetD11_1: D11.1(K) R107.2 R111.2
NetD12_1: D12.1(K) R109.2
NetD13_1: D13.1(K) D14.1(K) R120.1
NetQ1_1: Q1.1(B) R22.1
NetQ1_3: Q1.3(C) R1.2 R2.2
NetQ2_1: Q2.1(B) R24.1
NetQ2_3: Q2.3(C) R3.2 R4.2
NetQ3_1: Q3.1(B) R26.1
NetQ3_3: Q3.3(C) R5.2 R6.2
NetQ4_1: Q4.1(B) R28.1
NetQ4_3: Q4.3(C) R7.2 R8.2
NetQ5_1: Q5.1(B) R30.1
NetQ5_3: Q5.3(C) R9.2 R10.2
NetQ6_1: Q6.1(B) R32.1
NetQ6_3: Q6.3(C) R11.2 R12.2
NetQ7_1: Q7.1(B) R34.1
NetQ7_3: Q7.3(C) R13.2 R14.2
NetQ8_1: Q8.1(B) R36.1
NetQ8_3: Q8.3(C) R15.2 R16.2
NetQ9_1: Q9.1(B) R38.1
NetQ9_3: Q9.3(C) R17.2 R18.2
NetQ10_1: Q10.1(B) R40.1
NetQ10_3: Q10.3(C) R19.2 R20.2
NetQ11_1: Q11.1(B) R65.1
NetQ11_3: Q11.3(C) R42.2 R43.2
NetQ12_1: Q12.1(B) R67.1
NetQ12_3: Q12.3(C) R44.2 R45.2
NetQ13_1: Q13.1(B) R69.1
NetQ13_3: Q13.3(C) R46.2 R47.2
NetQ14_1: Q14.1(B) R71.1
NetQ14_3: Q14.3(C) R48.2 R49.2
NetQ15_1: Q15.1(B) R73.1
NetQ15_3: Q15.3(C) R50.2 R51.2
NetQ16_1: Q16.1(B) R75.1
NetQ16_3: Q16.3(C) R52.2 R53.2
NetQ17_1: Q17.1(B) R77.1
NetQ17_3: Q17.3(C) R54.2 R55.2
NetQ18_1: Q18.1(B) R79.1
NetQ18_3: Q18.3(C) R56.2 R57.2
NetQ19_1: Q19.1(B) R81.1
NetQ19_3: Q19.3(C) R58.2 R59.2
NetQ20_1: Q20.1(B) R83.1
NetQ20_3: Q20.3(C) R60.2 R61.2
NetQ21_1: Q21.1(B) R85.2 R86.1
NetQ21_3: Q21.3(C) R89.1
NetQ22_1: Q22.1(B) R87.2 R91.1
NetQ22_3: Q22.3(C) R92.1
NetQ23_1: Q23.1(B) R105.2
NetQ24_1: Q24.1(B) R106.2
NetQ25_2: Q25.2(E) R114.2
NetQ25_3: Q25.3(C) R115.2
NetQ26_1: Q26.1(B) R113.2
NetQ26_3: Q26.3(C) R118.1
NetQ27_1: Q27.1(B) R115.1 R116.1
NetQ27_2: Q27.2(E) R117.1
NetQ28_1: Q28.1(B) R122.1
NetQ28_3: Q28.3(C) R126.1
NetQ29_1: Q29.1(B) R119.2
NetQ29_3: Q29.3(C) R122.2
NetQ30_2: Q30.2(E) R125.1
NetQ30_3: Q30.3(C) R124.1
NetQ31_2: Q31.2(E) R128.2
NetQ31_3: Q31.3(C) R129.2
NetQ32_2: Q32.2(E) R132.2
NetQ32_3: Q32.3(C) R133.2
NetQ33_3: Q33.3(D) R137.1
NetQ34_1: Q34.1(B) R129.1 R130.1
NetQ34_2: Q34.2(E) R131.1
NetQ35_1: Q35.1(B) R133.1 R134.1
NetQ35_2: Q35.2(E) R135.1
NetR94_2: R94.2 U1.38(FUSE)
NetR95_2: R95.2 U2.38(FUSE)
NetR96_2: R96.2 U2.42(PACK)
NetR97_1: R97.1 U2.27(SDA)
NetR97_2: R97.2 R104.1 U3.7(SDA2)
NetR98_1: R98.1 U2.26(SCL)
NetR98_2: R98.2 R99.1 U3.6(SCL2)
NetR100_1: R100.1 R105.1 U1.37(BREG)
NetR101_1: R101.1 R106.1 U2.37(BREG)
NetR108_2: R108.2 R109.1

Not connected (* = marked no-connect by the designer): U1 1(NC) 3(NC) 5(NC) 7(NC) 9(NC) 11(NC) 19(NC) 39(PDSG) 40(PCHG) 43(DSG) 44(NC) 45(CHG); U2 1(NC) 3(NC) 5(NC) 7(NC) 9(NC) 11(NC) 19(NC) 40(PCHG) 44(NC)

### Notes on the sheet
- Top stack cell balancing
- Note: Switches on VCC1/2 are only for lower consumption.
- Note: If LDO is not default enabled, need to reserve connector for external 3.3V-VCC2
- If using bq7694202, be able to use MSP to do OTP.
- Different DDSG/DCHG :
  BOTAFE_DCHG circuit is more friendly to consumption, but BOTAFE_DDSG has to be high when DSG MOSFET off since
  BOTAFE_DDSG is also used to turn on Q47.
- (near R128) Bottom DDSG active high, top CFETOFF active low.
  If requring DSG MOSFET on, BOT_DDSG is low, TOPAFE_DFETOFF is high.  If bottom AFE requires DSG MOSFET off, pull high BOT_DDSG, TOPAFE_DFETOFF is pull low, Top AFE turns off DSG MOSFET.
  Bottom DCHG active low, top DFETOFF active low.
  If requring CHG MOSFET on, BOT_DCHG is high, TOPAFE_CFETOFF is high. If bottom AFE requires CHG MOSFET off, pull low BOT_DCHG, TOPAFE_CFETOFF is pull low, Top AFE turns off CHG MOSFET.
- Bot stack cell balancing
- If seperate 5V and 3.3V, need a Schottky to avoid leakage current inout LDO output PINs.
  Schottky has voltage drop when working in normal mode, causing current from AFE LDO.
- (near R62) R62: NC if two seperate VC10 wires from pack.
- N/A
- Could use NTCs to monitor if REGx shorted.

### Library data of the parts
C1-C10 C12-C21 = GRM155R71E104KE14D: CAP, CERM, 0.1 µF, 25 V,+/- 10%, X7R, 0402; Manufacturer: MuRata; Polarized: N; CompType: Capacitor; Value: 0.1uF; U/M: EA; Cap_F: 0.0000001; Tolerance_%: 10; VDC_V: 25; Value2: 25V; TaMin_C: -55; TaMax_C: 125; SizeArea_mm2: 0.5; SizeAreaWB_mm2: 3; SizeX_mm: 1; SizeZ_mm: 0.6; AEC Category: Q200; Green_Lifecycle: Active; Green_REACh: Passed
C11 C22 = GRM188R71H104KA93D: CAP, CERM, 0.1 µF, 50 V,+/- 10%, X7R, 0603; Manufacturer: MuRata; Polarized: N; CompType: Capacitor; Value: 0.1uF; U/M: EA; Cap_F: 0.0000001; Tolerance_%: 10; VDC_V: 50; Value2: 50V; TaMin_C: -55; TaMax_C: 125; Cap_Case: 0603; SizeArea_mm2: 1.28; SizeAreaWB_mm2: 4.68; SizeX_mm: 1.6; SizeY_mm: 0.8; SizeZ_mm: 1; AEC Category: Q200; Green_Lifecycle: Active; Green_REACh: Passed
C23 C24 = GRM31CR72A225KA73L: CAP, CERM, 2.2 µF, 100 V,+/- 10%, X7R, 1206; Manufacturer: Holy Stone Enterprise; Polarized: N; CompType: Capacitor; Value: 2.2uF; U/M: EA; Cap_F: 0.0000022; Tolerance_%: 10; VDC_V: 100; Value2: 100V; TaMin_C: -55; TaMax_C: 125; Cap_Case: 1206; SizeArea_mm2: 5.12; SizeAreaWB_mm2: 10.92; SizeX_mm: 3.2; SizeY_mm: 1.6; SizeZ_mm: 1.9; AEC Category: Q200; Green_Lifecycle: Active; Green_REACh: Passed
C25-C28 C38 C39 C50 = GRM1885C2A101JA01D: CAP, CERM, 100 pF, 100 V,+/- 5%, C0G/NP0, 0603; Manufacturer: MuRata; Polarized: N; CompType: Capacitor; Value: 100pF; U/M: EA; Cap_F: 0.0000000001; Tolerance_%: 5; VDC_V: 100; Value2: 100V; TaMin_C: -55; TaMax_C: 125; SizeArea_mm2: 1.28; SizeAreaWB_mm2: 4.68; SizeX_mm: 1.6; SizeY_mm: 0.8; SizeZ_mm: 1; AEC Category: Q200; Green_Lifecycle: Active; Green_REACh: Passed
C29 = GRM21BR71E225KA73L: CAP, CERM, 2.2 µF, 25 V,+/- 10%, X7R, 0805; Manufacturer: MuRata; Polarized: N; CompType: Capacitor; Value: 2.2uF; U/M: EA; Cap_F: 0.0000022; Tolerance_%: 10; ESR_ohm: 0.005; Value1: 0.005 ohm; VDC_V: 25; Value2: 25V; TaMin_C: -55; TaMax_C: 125; Cap_Case: 0805; SizeArea_mm2: 2.5; SizeAreaWB_mm2: 6.75; SizeX_mm: 2; SizeY_mm: 1.25; SizeZ_mm: 1.45; AEC Category: Q200; Green_Lifecycle: Active; Green_REACh: Passed
C30 C31 = EMK107BB7225MA-T: CAP, CERM, 2.2 µF, 16 V,+/- 10%, X7R, 0603; Manufacturer: Taiyo Yuden; Polarized: N; CompType: Capacitor; Value: 2.2uF; U/M: EA; Cap_F: 0.0000022; Tolerance_%: 10; VDC_V: 16; Value2: 16V; TaMin_C: -55; TaMax_C: 125; SizeArea_mm2: 1.28; SizeAreaWB_mm2: 4.68; SizeX_mm: 1.6; SizeY_mm: 0.8; SizeZ_mm: 1; AEC Category: Q200
C32-C35 = GCM188R71C105KA64D: CAP, CERM, 1 µF, 16 V,+/- 10%, X7R, AEC-Q200 Grade 1, 0603; Manufacturer: MuRata; Polarized: N; CompType: Capacitor; Value: 1uF; U/M: EA; Cap_F: 0.000001; Tolerance_%: 10; VDC_V: 16; Value2: 16V; TaMin_C: -55; TaMax_C: 125; SizeArea_mm2: 1.28; SizeAreaWB_mm2: 4.68; SizeX_mm: 1.6; SizeY_mm: 0.8; SizeZ_mm: 1; AEC Category: Q200; AEC Qualified: Y; Green_Lifecycle: Active; Green_REACh: Passed
C36 C37 C42 C43 C46 = GRM188R71H104KA93D: CAP, CERM, 0.1 µF, 50 V,+/- 10%, X7R, 0603; Manufacturer: MuRata; Polarized: N; CompType: Capacitor; Value: 0.1uF; U/M: EA; Cap_F: 0.0000001; Tolerance_%: 10; VDC_V: 50; Value2: 50V; TaMin_C: -55; TaMax_C: 125; SizeArea_mm2: 1.28; SizeAreaWB_mm2: 4.68; SizeX_mm: 1.6; SizeY_mm: 0.8; SizeZ_mm: 1; AEC Category: Q200; Green_Lifecycle: Active; Green_REACh: Passed
C40 = GRM188R71H223KA01D: CAP, CERM, 0.022 µF, 50 V,+/- 10%, X7R, 0603; Manufacturer: MuRata; Polarized: N; CompType: Capacitor; Value: 0.022uF; U/M: EA; Cap_F: 0.000000022; Tolerance_%: 10; VDC_V: 50; Value2: 50V; TaMin_C: -55; TaMax_C: 125; Cap_Case: 0603; SizeArea_mm2: 1.28; SizeAreaWB_mm2: 4.68; SizeX_mm: 1.6; SizeY_mm: 0.8; SizeZ_mm: 1; AEC Category: Q200; Green_Lifecycle: Active; Green_REACh: Passed
C41 = GRM188R71H223KA01D: CAP, CERM, 0.022 µF, 50 V,+/- 10%, X7R, 0603; Manufacturer: MuRata; Polarized: N; CompType: Capacitor; Value: 0.022uF; U/M: EA; Cap_F: 0.000000022; Tolerance_%: 10; VDC_V: 50; Value2: 50V; TaMin_C: -55; TaMax_C: 125; SizeArea_mm2: 1.28; SizeAreaWB_mm2: 4.68; SizeX_mm: 1.6; SizeY_mm: 0.8; SizeZ_mm: 1; AEC Category: Q200; Green_Lifecycle: Active; Green_REACh: Passed
C44 C45 = C3216X7R2A105K160AA: CAP, CERM, 1 µF, 100 V,+/- 10%, X7R, 1206; Manufacturer: TDK; Polarized: N; CompType: Capacitor; Value: 1uF; U/M: EA; Cap_F: 0.000001; Tolerance_%: 10; ESR_ohm: 0.004575; Value1: 0.004575 ohm; VDC_V: 100; Value2: 100V; IRMS_A: 3.39639; TaMin_C: -55; TaMax_C: 125; Cap_Case: 1206; SizeArea_mm2: 5.12; SizeAreaWB_mm2: 10.92; SizeX_mm: 3.2; SizeY_mm: 1.6; SizeZ_mm: 1.8; AEC Category: Q200
C47 C53 C56 = GRM1885C1H470JA01D: CAP, CERM, 47 pF, 50 V,+/- 5%, C0G/NP0, 0603; Manufacturer: MuRata; Polarized: N; CompType: Capacitor; Value: 47pF; U/M: EA; Cap_F: 0.000000000047; Tolerance_%: 5; VDC_V: 50; Value2: 50V; TaMin_C: -55; TaMax_C: 125; SizeArea_mm2: 1.28; SizeAreaWB_mm2: 4.68; SizeX_mm: 1.6; SizeY_mm: 0.8; SizeZ_mm: 1; AEC Category: Q200; Green_Lifecycle: Active; Green_REACh: Passed
C48 C49 C51 C52 C54 C55 = GRM188R71H471KA01D: CAP, CERM, 470 pF, 50 V,+/- 10%, X7R, 0603; Manufacturer: MuRata; Polarized: N; CompType: Capacitor; Value: 470pF; U/M: EA; Cap_F: 0.00000000047; Tolerance_%: 10; VDC_V: 50; Value2: 50V; TaMin_C: -55; TaMax_C: 125; SizeArea_mm2: 1.28; SizeAreaWB_mm2: 4.68; SizeX_mm: 1.6; SizeY_mm: 0.8; SizeZ_mm: 1; AEC Category: Q200; Green_Lifecycle: Active; Green_REACh: Passed
D1 D4 D6 D8 D9 D11 D12 = BAT46W-7-F: Diode, Schottky, 100 V, 0.15 A, SOD-123; Manufacturer: Diodes Inc.; U/M: EA; Vf_V: 0.6; Value: 100V; Value1: 0.15A; Value2: 0.6V; Io_A: 0.15; Vr_V: 100; SizeAreaWB_mm2: 13.095; SizeArea_mm2: 6.545; SizeX_mm: 3.85; SizeY_mm: 1.7; SizeZ_mm: 1.35; AEC Category: Q101; Green_Lifecycle: Active; Green_REACh: Passed
D2 D5 D10 D16 = BAT42WS-7-F: Diode, Schottky, 30 V, 0.2 A, SOD-323; Manufacturer: Diodes Inc.; U/M: EA; Vf_V: 1; Value: 30V; Value1: 0.2A; Value2: 1V; Io_A: 0.2; Vr_V: 30; SizeAreaWB_mm2: 8.695; SizeArea_mm2: 3.645; SizeX_mm: 2.7; SizeY_mm: 1.35; AEC Category: Q101; Green_Lifecycle: Not Set; Green_REACh: Incomplete
D3 D7 D15 = MMSZ4685T1G: Diode, Zener, 3.6 V, 500 mW, SOD-123; Manufacturer: ON Semiconductor; SymbolCreator: a0412235; U/M: EA; Power_W: 0.5; Vz_V: 3.6; Value1: 0.5W; RJA_CperW: 340; SizeAreaWB_mm2: 13.095; SizeArea_mm2: 6.545; SizeX_mm: 3.85; SizeY_mm: 1.7; SizeZ_mm: 1.35; AEC Category: Q101; Green_Lifecycle: Active; Green_REACh: Passed
D13 D14 = DB2J20900L: as D49 on sheet High level sch
Q1-Q20 = BSR14, Nexperia: Transistor, NPN, 40 V, 0.8 A, SOT-23; CompType: BJT; U/M: EA; Value: 40 V; Value1: 0.8 A; Value2: 300; SizeAreaWB_mm2: 14; SizeArea_mm2: 7.5; SizeX_mm: 2.5; SizeY_mm: 3; SizeZ_mm: 1.1; AEC Category: Q101; PNP: 0; NPN: 1; Vceo_V: 40; Vcesat1_V: 0.3; IcRated_A: 0.8; TaMin_C: -65; TaMax_C: 150
Q21 = BC846B,215, Nexperia: Transistor, NPN, 65 V, 0.1 A, SOT-23; CompType: BJT; PNP: 0; NPN: 1; Vceo_V: 65; Vcesat1_V: 0.09; Value: 65 V; IcRated_A: 0.1; Value1: 0.1 A; HfeMax: 450; TaMin_C: -65; TaMax_C: 150; SizeAreaWB_mm2: 14; SizeArea_mm2: 7.5; SizeX_mm: 2.5; SizeY_mm: 3; SizeZ_mm: 1.1; U/M: EA; AEC Category: Q101; AEC Qualified: N
Q22 Q25 Q26 Q29 Q31 Q32 = MMBTA05LT1G, ON Semiconductor: Transistor, NPN, 60 V, 0.5 A, AEC-Q101, SOT-23; CompType: BJT; PNP: 0; NPN: 1; Vceo_V: 60; Vcesat1_V: 0.25; Value: 60 V; IcRated_A: 0.5; Value1: 0.5 A; TaMin_C: -55; TaMax_C: 150; SizeAreaWB_mm2: 14; SizeArea_mm2: 7.5; SizeX_mm: 2.5; SizeY_mm: 3; SizeZ_mm: 1.1; U/M: EA; AEC Category: Q101; AEC Qualified: Y
Q23 Q24 = FZT493TA, Diodes Inc.: Transistor, NPN, 60 V, 1 A, SOT-223; SymbolCreator: a0412235; PNP: 0; NPN: 1; Vceo_V: 60; Vcesat1_V: 0.3; Value: 60V; Value1: 1 A; HfeMax: 300; TaMin_C: -55; TaMax_C: 150; SizeAreaWB_mm2: 76.5; SizeArea_mm2: 45.5; SizeX_mm: 6.5; SizeY_mm: 7; SizeZ_mm: 1.6; CompType: BJT; U/M: EA; AEC Category: Q101; AEC Qualified: Y
Q27 Q28 Q30 Q34 Q35 = MMBTA56LT1G, ON Semiconductor: Transistor, PNP, 80 V, 0.5 A, SOT-23; CompType: BJT; PNP: 1; NPN: 0; Vceo_V: 80; Vcesat1_V: 0.25; Value: 80 V; IcRated_A: 0.5; Value1: 0.5 A; TaMin_C: -55; TaMax_C: 150; SizeAreaWB_mm2: 14; SizeArea_mm2: 7.5; SizeX_mm: 2.5; SizeY_mm: 3; SizeZ_mm: 1.1; U/M: EA; AEC Category: Q101
Q33 = DMG1013UW-7: MOSFET, P-CH, -20 V, -0.82 A, SOT-323; Manufacturer: Diodes Inc.; Alternate Manufacturer: None; SymbolCreator: a0411947; U/M: EA; ChType: P; Value: -20V; Value1: 0.75 ohm; Rdson45_ohm: 0.75; Value2: 0.622 nC; QgTyp_nC: 0.622; Vgs_V: -6; SizeAreaWB_mm2: 10.24; SizeArea_mm2: 4.84; SizeX_mm: 2.2; SizeZ_mm: 1.1; AEC Category: Q101; Green_Lifecycle: Active; Green_REACh: Passed
R1-R20 R42-R61 = CRCW120680R6FKEA: RES, 80.6, 1%, 0.25 W, 1206; Manufacturer: Vishay-Dale; CompType: Resistor; Value: 80.6; Value_Code: 80R6; Tolerance_%: 1; Power_W: 0.25; Value2: 0.25W; VDC_V: 200; TempCo: 100 ppm/C; SizeArea_mm2: 5.12; SizeX_mm: 3.2; SizeY_mm: 1.6; SizeZ_mm: 1.35; EIA_Code: E96; U/M: EA; AEC Category: Q200
R21 R23 R25 R27 R29 R31 R33 R35 R37 R39 R64 R66 R68 R70 R72 R74 R76 R78 R80 R82 R88 R90 R97 R98 R102 R103 R105 R106 = CRCW0603100RFKEA: RES, 100, 1%, 0.1 W, 0603; Manufacturer: Vishay-Dale; CompType: Resistor; Value: 100; Value_Code: 100R; Tolerance_%: 1; Power_W: 0.1; Value2: 0.1W; VDC_V: 75; TempCo: 100 ppm/C; SizeArea_mm2: 1.28; SizeX_mm: 1.6; SizeY_mm: 0.8; EIA_Code: E96; U/M: EA; AEC Category: Q200; Green_Lifecycle: Active; Green_REACh: Passed
R22 R24 R26 R28 R30 R32 R34 R36 R38 R40 R65 R67 R69 R71 R73 R75 R77 R79 R81 R83 = CRCW0603300RJNEA: RES, 300, 5%, 0.1 W, 0603; Manufacturer: Vishay-Dale; CompType: Resistor; Value: 300; Value_Code: 300R; Tolerance_%: 5; Power_W: 0.1; Value2: 0.1W; VDC_V: 75; TempCo: 200 ppm/C; SizeArea_mm2: 1.28; SizeX_mm: 1.6; SizeY_mm: 0.8; SizeZ_mm: 1; EIA_Code: E24; U/M: EA; AEC Category: Q200; Green_Lifecycle: Active; Green_REACh: Passed
R41 R84 = CRCW060320R0FKEA: RES, 20.0, 1%, 0.1 W, 0603; Manufacturer: Vishay-Dale; CompType: Resistor; Value: 20.0; Res_ohm: 20; Value_Code: 20R0; Tolerance_%: 1; Power_W: 0.1; Value2: 0.1W; VDC_V: 75; TempCo: 100 ppm/C; SizeArea_mm2: 1.28; SizeX_mm: 1.6; SizeY_mm: 0.8; EIA_Code: E96; U/M: EA; AEC Category: Q200; Green_Lifecycle: Active; Green_REACh: Passed
R62 R63 R120 = CRCW06030000Z0EA: as R217 on sheet High level sch
R85 R87 R94-R96 R110 = CRCW060310K0FKEA: RES, 10.0 k, 1%, 0.1 W, 0603; Manufacturer: Vishay-Dale; CompType: Resistor; Value: 10.0k; Res_ohm: 10000; Value_Code: 10k0; Tolerance_%: 1; Power_W: 0.1; Value2: 0.1W; VDC_V: 75; TempCo: 100 ppm/C; SizeArea_mm2: 1.28; SizeX_mm: 1.6; SizeY_mm: 0.8; EIA_Code: E96; U/M: EA; AEC Category: Q200; Green_Lifecycle: Active; Green_REACh: Passed
R86 R91 R100 R101 = CRCW060310M0JNEA: RES, 10 M, 5%, 0.1 W, 0603; Manufacturer: Vishay-Dale; CompType: Resistor; Value: 10Meg; Res_ohm: 10000000; Value_Code: 10M0; Tolerance_%: 5; Power_W: 0.1; Value2: 0.1W; VDC_V: 75; TempCo: 200 ppm/C; SizeArea_mm2: 1.28; SizeX_mm: 1.6; SizeY_mm: 0.8; SizeZ_mm: 1; EIA_Code: E24; U/M: EA; AEC Category: Q200; Green_Lifecycle: Active; Green_REACh: Passed
R89 = RC0603FR-072ML: RES, 2.00 M, 1%, 0.1 W, 0603; Manufacturer: Yageo America; CompType: Resistor; Value: 2.00Meg; Res_ohm: 2000000; Value_Code: 2M00; Tolerance_%: 1; Power_W: 0.1; Value2: 0.1W; VDC_V: 150; TempCo: 200 ppm/C; SizeArea_mm2: 1.28; SizeX_mm: 1.6; SizeY_mm: 0.8; EIA_Code: E96; U/M: EA; AEC Category: Q200; Green_Lifecycle: Active; Green_REACh: Passed
R92 R93 = CRCW0603499KFKEA: RES, 499 k, 1%, 0.1 W, 0603; Manufacturer: Vishay-Dale; CompType: Resistor; Value: 499k; Res_ohm: 499000; Tolerance_%: 1; Power_W: 0.1; Value2: 0.1W; VDC_V: 75; TempCo: 100 ppm/C; SizeArea_mm2: 1.28; SizeX_mm: 1.6; SizeY_mm: 0.8; EIA_Code: E96; U/M: EA; AEC Category: Q200; Green_Lifecycle: Active; Green_REACh: Passed
R99 R104 = RC0603FR-074K7L: RES, 4.70 k, 1%, 0.1 W, 0603; Manufacturer: Yageo America; CompType: Resistor; Value: 4.70k; Res_ohm: 4700; Value_Code: 4k70; Tolerance_%: 1; Power_W: 0.1; Value2: 0.1W; VDC_V: 150; TempCo: 200 ppm/C; SizeArea_mm2: 1.28; SizeX_mm: 1.6; SizeY_mm: 0.8; U/M: EA; AEC Category: Q200; Green_Lifecycle: Active; Green_REACh: Passed
R107 R111 = CRCW1206619RFKEA: RES, 619, 1%, 0.25 W, 1206; Manufacturer: Yageo; CompType: Resistor; Value: 619; Value_Code: 619R; Tolerance_%: 1; Power_W: 0.25; Value2: 0.25W; VDC_V: 200; TempCo: 100 ppm/C; SizeArea_mm2: 5.12; SizeX_mm: 3.2; SizeY_mm: 1.6; SizeZ_mm: 1.35; EIA_Code: E96; U/M: EA; AEC Category: Q200
R108 R109 = CRCW1206154RFKEA: RES, 154, 1%, 0.25 W, 1206; Manufacturer: Yageo; CompType: Resistor; Value: 154; Value_Code: 154R; Tolerance_%: 1; Power_W: 0.25; Value2: 0.25W; VDC_V: 200; TempCo: 100 ppm/C; SizeArea_mm2: 5.12; SizeX_mm: 3.2; SizeY_mm: 1.6; SizeZ_mm: 1.35; EIA_Code: E96; U/M: EA; AEC Category: Q200
R112 R118 = CRCW2512200RJNEG: RES, 200, 5%, 1 W, AEC-Q200 Grade 0, 2512; Manufacturer: Yageo; CompType: Resistor; Value: 200; Value_Code: 200R; Tolerance_%: 5; Power_W: 1; Value2: 1W; VDC_V: 500; TempCo: 200 ppm/C; SizeArea_mm2: 20.16; SizeX_mm: 6.3; SizeY_mm: 3.2; SizeZ_mm: 0.71; EIA_Code: E24; U/M: EA; AEC Category: Q200; AEC Qualified: Y; AEC Grade: 0; Green_Lifecycle: Active; Green_REACh: Passed
R113 = RC0603FR-072KL: RES, 2.00 k, 1%, 0.1 W, 0603; Manufacturer: Yageo America; CompType: Resistor; Value: 2.00k; Res_ohm: 2000; Value_Code: 2k00; Tolerance_%: 1; Power_W: 0.1; Value2: 0.1W; VDC_V: 150; TempCo: 200 ppm/C; SizeArea_mm2: 1.28; SizeX_mm: 1.6; SizeY_mm: 0.8; EIA_Code: E96; U/M: EA; AEC Category: Q200; Green_Lifecycle: Active; Green_REACh: Passed
R114 R128 R132 R136 R138 = CRCW0603150KFKEA: RES, 150 k, 1%, 0.1 W, 0603; Manufacturer: Vishay-Dale; CompType: Resistor; Value: 150k; Res_ohm: 150000; Tolerance_%: 1; Power_W: 0.1; Value2: 0.1W; VDC_V: 75; TempCo: 100 ppm/C; SizeArea_mm2: 1.28; SizeX_mm: 1.6; SizeY_mm: 0.8; EIA_Code: E96; U/M: EA; AEC Category: Q200; Green_Lifecycle: Active; Green_REACh: Passed
R115 R119 R122 R124 R127 R129 R133 = CRCW0603200KFKEA: RES, 200 k, 1%, 0.1 W, 0603; Manufacturer: Vishay-Dale; CompType: Resistor; Value: 200k; Res_ohm: 200000; Tolerance_%: 1; Power_W: 0.1; Value2: 0.1W; VDC_V: 75; TempCo: 100 ppm/C; SizeArea_mm2: 1.28; SizeX_mm: 1.6; SizeY_mm: 0.8; EIA_Code: E96; U/M: EA; AEC Category: Q200; Green_Lifecycle: Active; Green_REACh: Passed
R116 R130 R134 = CRCW060380K6FKEA: RES, 80.6 k, 1%, 0.1 W, 0603; Manufacturer: Vishay-Dale; CompType: Resistor; Value: 80.6k; Res_ohm: 80600; Value_Code: 80k6; Tolerance_%: 1; Power_W: 0.1; Value2: 0.1W; VDC_V: 75; TempCo: 100 ppm/C; SizeArea_mm2: 1.28; SizeX_mm: 1.6; SizeY_mm: 0.8; EIA_Code: E96; U/M: EA; AEC Category: Q200; Green_Lifecycle: Active; Green_REACh: Passed
R117 R131 R135 = RC0603FR-07300RL: RES, 300, 1%, 0.1 W, 0603; Manufacturer: Yageo America; CompType: Resistor; Value: 300; Value_Code: 300R; Tolerance_%: 1; Power_W: 0.1; Value2: 0.1W; VDC_V: 150; TempCo: 200 ppm/C; SizeArea_mm2: 1.28; SizeX_mm: 1.6; SizeY_mm: 0.8; U/M: EA; AEC Category: Q200; Green_Lifecycle: Active; Green_REACh: Passed
R121 = CRCW0603330KJNEA: RES, 330 k, 5%, 0.1 W, 0603; Manufacturer: Vishay-Dale; CompType: Resistor; Value: 330k; Res_ohm: 330000; Tolerance_%: 5; Power_W: 0.1; Value2: 0.1W; VDC_V: 75; TempCo: 200 ppm/C; SizeArea_mm2: 1.28; SizeX_mm: 1.6; SizeY_mm: 0.8; SizeZ_mm: 1; EIA_Code: E24; U/M: EA; AEC Category: Q200; Green_Lifecycle: Active; Green_REACh: Passed
R123 = RC0603FR-0733KL: RES, 33.0 k, 1%, 0.1 W, 0603; Manufacturer: Yageo America; CompType: Resistor; Value: 33.0k; Res_ohm: 33000; Value_Code: 33k0; Tolerance_%: 1; Power_W: 0.1; Value2: 0.1W; VDC_V: 150; TempCo: 200 ppm/C; SizeArea_mm2: 1.28; SizeX_mm: 1.6; SizeY_mm: 0.8; U/M: EA; AEC Category: Q200; Green_Lifecycle: Active; Green_REACh: Passed
R125 = CRCW060326K1FKEA: RES, 26.1 k, 1%, 0.1 W, 0603; Manufacturer: Vishay-Dale; CompType: Resistor; Value: 26.1k; Res_ohm: 26100; Value_Code: 26k1; Tolerance_%: 1; Power_W: 0.1; Value2: 0.1W; VDC_V: 75; TempCo: 100 ppm/C; SizeArea_mm2: 1.28; SizeX_mm: 1.6; SizeY_mm: 0.8; EIA_Code: E96; U/M: EA; AEC Category: Q200; Green_Lifecycle: Active; Green_REACh: Passed
R126 R137 = RC0603FR-0710RL: as R218 on sheet High level sch
RT1-RT6 = 103AT-2: THERMISTOR NTC 10KOHM BEAD; Manufacturer: Cantherm; Tolerance_%: 1; Power_W: 0.01; TaMin_C: -50; TaMax_C: 110; U/M: EA; Value: 10.0k ohm
U1 U2 = CMP-0750064-1: Multicell Battery Monitor and Protection Family, PFB0048A (TQFP-48); Alternate PartNumber: BQ76942PFBT; Alternate Manufacturer: Texas Instruments; SizeZ_mm: 1.2; SizeX_mm: 9; AEC Qualified: N; CompType: IC; SizeAreaWB_mm2: 121; SizeArea_mm2: 81; AEC Category: Q200
U3 = CMP-0091761-1: I²C Digital Isolator 3000Vrms 2 Channel  50kV/µs CMTI 8-SOIC (0.154", 3.90mm Width); Manufacturer: Texas Instruments; TaMin_C: -40°C; AEC Qualified: No; Standoff Height: 0.11mm; Min Supply Voltage: 2.25V; SizeZ_mm: 1.75mm; Nominal Supply Current: 2.7-5.3mA; Interface: I2C; TaMax_C: +125°C; TJmax_C: +150°C; Max Supply Voltage: 5.5V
